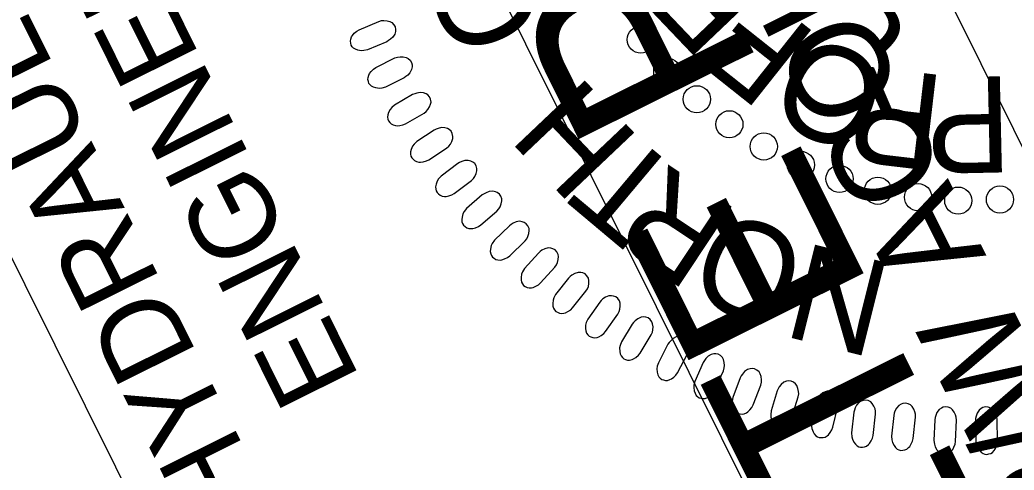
# Model space of a CAD drawing. Extents: x 475112 to 476842, y 500772 to 502767.
# Drawn here: x 475196.2 to 475254.8, y 502233.4 to 502259.9 of the extents above; entities that cross this region are included whole.
import ezdxf

# ---------------------------------------------------------------- set-up
doc = ezdxf.new("R2010")
doc.units = 0
for name, color, linetype in [('Sheet PE Seal Cell', 7, 'Continuous'), ('Sheet Plan CELL', 7, 'Continuous'), ('Sheet Sticker Incomplete CELL', 7, 'Continuous')]:
    doc.layers.add(name, color=color, linetype=linetype)

msp = doc.modelspace()

# ---------------------------------------------------------------- linework, layer by layer
at = {"layer": 'Sheet PE Seal Cell'}
for points in [[(475217.805, 502258.639), (475216.674, 502258.163), (475216.457, 502258.112), (475216.309, 502258.107), (475216.109, 502258.144), (475215.97, 502258.191), (475215.853, 502258.264), (475215.776, 502258.345), (475215.714, 502258.441), (475215.689, 502258.552), (475215.67, 502258.673), (475215.684, 502258.793), (475215.735, 502258.928), (475215.786, 502259.014), (475215.898, 502259.135), (475216.04, 502259.259), (475216.178, 502259.342), (475217.334, 502259.836), (475217.499, 502259.881), (475217.645, 502259.894), (475217.826, 502259.873), (475217.998, 502259.824), (475218.11, 502259.765), (475218.226, 502259.644), (475218.303, 502259.514), (475218.324, 502259.36), (475218.318, 502259.244), (475218.276, 502259.089), (475218.166, 502258.913), (475218.027, 502258.781), (475217.918, 502258.703)], [(475218.832, 502256.515), (475217.733, 502255.969), (475217.52, 502255.905), (475217.371, 502255.89), (475217.17, 502255.915), (475217.028, 502255.953), (475216.907, 502256.018), (475216.825, 502256.094), (475216.757, 502256.186), (475216.725, 502256.295), (475216.698, 502256.415), (475216.705, 502256.535), (475216.748, 502256.673), (475216.793, 502256.763), (475216.897, 502256.889), (475217.031, 502257.023), (475217.164, 502257.114), (475218.286, 502257.68), (475218.448, 502257.736), (475218.593, 502257.757), (475218.776, 502257.748), (475218.951, 502257.71), (475219.065, 502257.658), (475219.189, 502257.544), (475219.273, 502257.419), (475219.304, 502257.268), (475219.306, 502257.152), (475219.274, 502256.993), (475219.174, 502256.811), (475219.044, 502256.671), (475218.941, 502256.586)], [(475219.336, 502255.52), (475218.274, 502254.907), (475218.103, 502254.764), (475218.009, 502254.65), (475217.917, 502254.467), (475217.871, 502254.328), (475217.858, 502254.191), (475217.876, 502254.081), (475217.915, 502253.974), (475217.988, 502253.887), (475218.074, 502253.798), (475218.178, 502253.737), (475218.317, 502253.697), (475218.416, 502253.685), (475218.579, 502253.701), (475218.764, 502253.739), (475218.913, 502253.8), (475220.005, 502254.422), (475220.141, 502254.526), (475220.239, 502254.635), (475220.333, 502254.792), (475220.397, 502254.96), (475220.418, 502255.083), (475220.391, 502255.25), (475220.334, 502255.389), (475220.224, 502255.499), (475220.128, 502255.564), (475219.979, 502255.624), (475219.772, 502255.643), (475219.583, 502255.611), (475219.456, 502255.572)], [(475220.603, 502253.427), (475219.582, 502252.748), (475219.42, 502252.596), (475219.333, 502252.475), (475219.253, 502252.287), (475219.216, 502252.146), (475219.212, 502252.009), (475219.236, 502251.899), (475219.282, 502251.794), (475219.361, 502251.712), (475219.452, 502251.629), (475219.559, 502251.575), (475219.7, 502251.543), (475219.8, 502251.538), (475219.962, 502251.564), (475220.144, 502251.614), (475220.29, 502251.684), (475221.34, 502252.373), (475221.469, 502252.486), (475221.56, 502252.601), (475221.644, 502252.763), (475221.698, 502252.934), (475221.71, 502253.059), (475221.674, 502253.223), (475221.607, 502253.359), (475221.491, 502253.461), (475221.392, 502253.521), (475221.238, 502253.571), (475221.031, 502253.577), (475220.844, 502253.533), (475220.72, 502253.486)], [(475221.993, 502251.459), (475221.017, 502250.718), (475220.865, 502250.555), (475220.784, 502250.429), (475220.718, 502250.237), (475220.689, 502250.093), (475220.693, 502249.956), (475220.725, 502249.848), (475220.777, 502249.746), (475220.86, 502249.669), (475220.957, 502249.593), (475221.067, 502249.545), (475221.211, 502249.522), (475221.31, 502249.523), (475221.47, 502249.56), (475221.649, 502249.621), (475221.79, 502249.699), (475222.795, 502250.454), (475222.916, 502250.574), (475223.001, 502250.694), (475223.073, 502250.862), (475223.116, 502251.036), (475223.121, 502251.162), (475223.074, 502251.323), (475222.999, 502251.454), (475222.877, 502251.549), (475222.774, 502251.602), (475222.618, 502251.643), (475222.411, 502251.636), (475222.227, 502251.58), (475222.106, 502251.526)], [(475223.443, 502249.605), (475222.514, 502248.804), (475222.373, 502248.632), (475222.301, 502248.501), (475222.246, 502248.305), (475222.227, 502248.16), (475222.24, 502248.023), (475222.277, 502247.917), (475222.336, 502247.82), (475222.424, 502247.747), (475222.525, 502247.677), (475222.639, 502247.637), (475222.783, 502247.623), (475222.882, 502247.629), (475223.04, 502247.677), (475223.214, 502247.749), (475223.35, 502247.836), (475224.305, 502248.652), (475224.419, 502248.779), (475224.495, 502248.905), (475224.558, 502249.077), (475224.59, 502249.253), (475224.586, 502249.379), (475224.53, 502249.537), (475224.447, 502249.663), (475224.319, 502249.75), (475224.213, 502249.797), (475224.054, 502249.827), (475223.848, 502249.807), (475223.668, 502249.741), (475223.551, 502249.679)], [(475225.037, 502247.792), (475224.161, 502246.933), (475224.031, 502246.754), (475223.968, 502246.618), (475223.925, 502246.42), (475223.914, 502246.273), (475223.936, 502246.138), (475223.981, 502246.034), (475224.045, 502245.941), (475224.138, 502245.874), (475224.243, 502245.81), (475224.358, 502245.777), (475224.503, 502245.772), (475224.602, 502245.786), (475224.756, 502245.842), (475224.926, 502245.925), (475225.056, 502246.021), (475225.959, 502246.895), (475226.064, 502247.03), (475226.132, 502247.159), (475226.183, 502247.335), (475226.205, 502247.513), (475226.194, 502247.638), (475226.126, 502247.792), (475226.036, 502247.913), (475225.903, 502247.992), (475225.794, 502248.032), (475225.634, 502248.052), (475225.429, 502248.019), (475225.254, 502247.942), (475225.14, 502247.872)], [(475226.748, 502246.185), (475225.928, 502245.273), (475225.809, 502245.085), (475225.754, 502244.946), (475225.724, 502244.745), (475225.723, 502244.599), (475225.753, 502244.465), (475225.804, 502244.365), (475225.875, 502244.275), (475225.971, 502244.215), (475226.08, 502244.157), (475226.198, 502244.131), (475226.342, 502244.135), (475226.44, 502244.155), (475226.59, 502244.221), (475226.755, 502244.315), (475226.878, 502244.418), (475227.724, 502245.347), (475227.821, 502245.488), (475227.88, 502245.622), (475227.921, 502245.801), (475227.931, 502245.979), (475227.912, 502246.104), (475227.835, 502246.254), (475227.737, 502246.368), (475227.599, 502246.438), (475227.489, 502246.471), (475227.327, 502246.482), (475227.125, 502246.437), (475226.955, 502246.348), (475226.846, 502246.271)], [(475228.526, 502244.704), (475227.765, 502243.743), (475227.658, 502243.548), (475227.612, 502243.406), (475227.594, 502243.203), (475227.603, 502243.057), (475227.641, 502242.925), (475227.698, 502242.828), (475227.774, 502242.743), (475227.874, 502242.689), (475227.986, 502242.638), (475228.105, 502242.62), (475228.25, 502242.633), (475228.346, 502242.659), (475228.492, 502242.734), (475228.65, 502242.838), (475228.767, 502242.949), (475229.552, 502243.93), (475229.641, 502244.077), (475229.692, 502244.214), (475229.72, 502244.395), (475229.719, 502244.574), (475229.693, 502244.696), (475229.607, 502244.841), (475229.502, 502244.95), (475229.36, 502245.011), (475229.247, 502245.037), (475229.086, 502245.038), (475228.887, 502244.979), (475228.722, 502244.88), (475228.618, 502244.797)], [(475230.362, 502243.291), (475229.662, 502242.283), (475229.567, 502242.081), (475229.531, 502241.937), (475229.526, 502241.734), (475229.543, 502241.588), (475229.59, 502241.459), (475229.653, 502241.367), (475229.734, 502241.286), (475229.837, 502241.239), (475229.953, 502241.195), (475230.073, 502241.184), (475230.216, 502241.207), (475230.31, 502241.238), (475230.451, 502241.322), (475230.603, 502241.436), (475230.712, 502241.554), (475231.435, 502242.582), (475231.513, 502242.734), (475231.555, 502242.874), (475231.573, 502243.056), (475231.561, 502243.235), (475231.526, 502243.356), (475231.432, 502243.495), (475231.32, 502243.596), (475231.175, 502243.649), (475231.06, 502243.668), (475230.899, 502243.658), (475230.704, 502243.587), (475230.546, 502243.478), (475230.448, 502243.389)], [(475232.283, 502241.993), (475231.648, 502240.943), (475231.566, 502240.736), (475231.538, 502240.59), (475231.546, 502240.387), (475231.573, 502240.243), (475231.627, 502240.117), (475231.696, 502240.028), (475231.782, 502239.953), (475231.888, 502239.911), (475232.006, 502239.876), (475232.126, 502239.872), (475232.267, 502239.903), (475232.36, 502239.941), (475232.495, 502240.034), (475232.639, 502240.157), (475232.741, 502240.282), (475233.398, 502241.353), (475233.467, 502241.51), (475233.501, 502241.653), (475233.506, 502241.835), (475233.483, 502242.013), (475233.441, 502242.131), (475233.337, 502242.264), (475233.22, 502242.358), (475233.071, 502242.402), (475232.956, 502242.413), (475232.796, 502242.394), (475232.606, 502242.31), (475232.455, 502242.191), (475232.363, 502242.096)], [(475234.386, 502240.805), (475233.818, 502239.717), (475233.75, 502239.506), (475233.731, 502239.358), (475233.752, 502239.155), (475233.788, 502239.013), (475233.85, 502238.891), (475233.925, 502238.806), (475234.015, 502238.737), (475234.123, 502238.703), (475234.243, 502238.674), (475234.363, 502238.679), (475234.503, 502238.719), (475234.593, 502238.762), (475234.722, 502238.863), (475234.858, 502238.994), (475234.951, 502239.126), (475235.54, 502240.236), (475235.598, 502240.397), (475235.624, 502240.541), (475235.618, 502240.724), (475235.583, 502240.9), (475235.534, 502241.016), (475235.422, 502241.141), (475235.299, 502241.228), (475235.148, 502241.262), (475235.033, 502241.266), (475234.873, 502241.237), (475234.689, 502241.142), (475234.546, 502241.014), (475234.459, 502240.912)], [(475236.467, 502239.739), (475235.969, 502238.618), (475235.914, 502238.403), (475235.905, 502238.254), (475235.938, 502238.054), (475235.982, 502237.914), (475236.052, 502237.795), (475236.132, 502237.717), (475236.227, 502237.653), (475236.337, 502237.625), (475236.459, 502237.605), (475236.578, 502237.616), (475236.715, 502237.665), (475236.802, 502237.713), (475236.924, 502237.823), (475237.052, 502237.962), (475237.137, 502238.1), (475237.655, 502239.244), (475237.703, 502239.408), (475237.718, 502239.554), (475237.702, 502239.736), (475237.656, 502239.909), (475237.599, 502240.022), (475237.48, 502240.14), (475237.351, 502240.219), (475237.199, 502240.243), (475237.083, 502240.241), (475236.927, 502240.201), (475236.749, 502240.095), (475236.614, 502239.958), (475236.534, 502239.852)], [(475238.642, 502238.824), (475238.214, 502237.674), (475238.173, 502237.455), (475238.173, 502237.306), (475238.219, 502237.108), (475238.272, 502236.972), (475238.349, 502236.858), (475238.434, 502236.784), (475238.532, 502236.726), (475238.644, 502236.706), (475238.767, 502236.692), (475238.885, 502236.712), (475239.018, 502236.769), (475239.102, 502236.823), (475239.217, 502236.94), (475239.336, 502237.087), (475239.412, 502237.228), (475239.857, 502238.404), (475239.895, 502238.571), (475239.901, 502238.717), (475239.873, 502238.898), (475239.816, 502239.069), (475239.754, 502239.177), (475239.627, 502239.288), (475239.493, 502239.358), (475239.34, 502239.373), (475239.224, 502239.363), (475239.07, 502239.314), (475238.899, 502239.197), (475238.774, 502239.051), (475238.7, 502238.941)], [(475240.822, 502238.052), (475240.469, 502236.878), (475240.441, 502236.657), (475240.451, 502236.508), (475240.509, 502236.313), (475240.57, 502236.18), (475240.655, 502236.071), (475240.743, 502236.003), (475240.845, 502235.952), (475240.958, 502235.938), (475241.081, 502235.933), (475241.198, 502235.959), (475241.328, 502236.025), (475241.408, 502236.084), (475241.516, 502236.208), (475241.625, 502236.362), (475241.693, 502236.508), (475242.062, 502237.71), (475242.09, 502237.878), (475242.087, 502238.025), (475242.047, 502238.204), (475241.98, 502238.369), (475241.91, 502238.474), (475241.777, 502238.577), (475241.64, 502238.639), (475241.485, 502238.644), (475241.371, 502238.626), (475241.22, 502238.568), (475241.056, 502238.44), (475240.94, 502238.287), (475240.875, 502238.172)], [(475243.141, 502237.403), (475242.861, 502236.209), (475242.848, 502235.987), (475242.866, 502235.839), (475242.937, 502235.648), (475243.007, 502235.519), (475243.098, 502235.416), (475243.19, 502235.354), (475243.295, 502235.309), (475243.409, 502235.302), (475243.532, 502235.305), (475243.648, 502235.338), (475243.772, 502235.412), (475243.849, 502235.476), (475243.948, 502235.606), (475244.048, 502235.768), (475244.106, 502235.917), (475244.4, 502237.139), (475244.417, 502237.31), (475244.404, 502237.456), (475244.353, 502237.632), (475244.276, 502237.793), (475244.199, 502237.893), (475244.06, 502237.987), (475243.92, 502238.04), (475243.765, 502238.035), (475243.652, 502238.011), (475243.505, 502237.943), (475243.35, 502237.805), (475243.243, 502237.646), (475243.185, 502237.526)], [(475245.344, 502236.796), (475245.206, 502235.577), (475245.219, 502235.355), (475245.255, 502235.21), (475245.348, 502235.029), (475245.432, 502234.909), (475245.534, 502234.818), (475245.634, 502234.767), (475245.743, 502234.734), (475245.857, 502234.741), (475245.979, 502234.758), (475246.09, 502234.805), (475246.205, 502234.893), (475246.273, 502234.965), (475246.357, 502235.106), (475246.437, 502235.278), (475246.477, 502235.434), (475246.625, 502236.682), (475246.622, 502236.853), (475246.592, 502236.997), (475246.521, 502237.165), (475246.426, 502237.316), (475246.337, 502237.407), (475246.188, 502237.484), (475246.043, 502237.52), (475245.889, 502237.497), (475245.78, 502237.46), (475245.642, 502237.375), (475245.505, 502237.22), (475245.417, 502237.049), (475245.373, 502236.923)], [(475247.696, 502236.609), (475247.568, 502235.39), (475247.582, 502235.168), (475247.619, 502235.023), (475247.713, 502234.842), (475247.799, 502234.723), (475247.902, 502234.632), (475248.002, 502234.582), (475248.112, 502234.55), (475248.225, 502234.559), (475248.347, 502234.576), (475248.458, 502234.624), (475248.572, 502234.713), (475248.64, 502234.786), (475248.723, 502234.928), (475248.801, 502235.1), (475248.839, 502235.256), (475248.977, 502236.505), (475248.973, 502236.676), (475248.943, 502236.82), (475248.87, 502236.988), (475248.773, 502237.138), (475248.685, 502237.228), (475248.535, 502237.304), (475248.388, 502237.339), (475248.236, 502237.315), (475248.126, 502237.276), (475247.989, 502237.19), (475247.853, 502237.034), (475247.767, 502236.863), (475247.724, 502236.737)], [(475250.111, 502236.355), (475250.06, 502235.129), (475250.088, 502234.908), (475250.135, 502234.766), (475250.24, 502234.592), (475250.333, 502234.479), (475250.441, 502234.394), (475250.544, 502234.35), (475250.655, 502234.326), (475250.768, 502234.341), (475250.889, 502234.366), (475250.996, 502234.421), (475251.104, 502234.517), (475251.167, 502234.594), (475251.241, 502234.74), (475251.308, 502234.917), (475251.337, 502235.076), (475251.397, 502236.331), (475251.382, 502236.501), (475251.342, 502236.643), (475251.259, 502236.806), (475251.153, 502236.95), (475251.059, 502237.034), (475250.905, 502237.1), (475250.756, 502237.126), (475250.606, 502237.092), (475250.499, 502237.048), (475250.367, 502236.953), (475250.241, 502236.789), (475250.167, 502236.612), (475250.131, 502236.484)], [(475252.506, 502236.308), (475252.533, 502235.081), (475252.574, 502234.863), (475252.63, 502234.724), (475252.745, 502234.557), (475252.845, 502234.449), (475252.959, 502234.372), (475253.064, 502234.334), (475253.177, 502234.317), (475253.289, 502234.339), (475253.408, 502234.372), (475253.51, 502234.433), (475253.613, 502234.535), (475253.671, 502234.617), (475253.735, 502234.768), (475253.791, 502234.949), (475253.811, 502235.108), (475253.791, 502236.366), (475253.765, 502236.534), (475253.717, 502236.672), (475253.624, 502236.83), (475253.509, 502236.967), (475253.41, 502237.045), (475253.252, 502237.102), (475253.102, 502237.118), (475252.954, 502237.075), (475252.85, 502237.023), (475252.725, 502236.921), (475252.609, 502236.749), (475252.546, 502236.568), (475252.519, 502236.437)]]:
    msp.add_lwpolyline(points, close=True, dxfattribs=at)
for centre in [(475232.784, 502258.762), (475234.346, 502256.871), (475236.087, 502255.247), (475238.006, 502253.772), (475240.033, 502252.467), (475242.221, 502251.376), (475244.499, 502250.552), (475246.759, 502249.852), (475249.127, 502249.473), (475251.496, 502249.272), (475253.955, 502249.338)]:
    msp.add_circle(centre, 0.801, dxfattribs=at)
at = {"layer": 'Sheet Plan CELL'}
msp.add_lwpolyline([(475217.863, 502201.351), (475173.331, 502290.874), (475274.068, 502340.984), (475318.607, 502251.45)], close=True, dxfattribs=at)
at = {"layer": 'Sheet Sticker Incomplete CELL'}
msp.add_lwpolyline([(475300.957, 502160.586), (475279.915, 502150.122), (475214.46, 502281.746), (475235.502, 502292.21)], close=True, dxfattribs=at)

# ---------------------------------------------------------------- texts
at = {"layer": 'Sheet PE Seal Cell'}
for s, rotation, p in [('E', 133.60936, (475240.42, 502261.294)), ('C', 114.02842, (475227.351, 502259.607)), ('F', 141.54916, (475243.307, 502258.943)), ('O', 157.42876, (475247.764, 502257.03)), ('R', 173.30835, (475250.807, 502256.63)), ('H', 133.49649, (475232.825, 502252.83)), ('P', 181.24815, (475254.568, 502256.616)), ('T', 139.98584, (475235.503, 502250.612)), ('R', 146.4752, (475238.655, 502248.582)), ('O', 159.45391, (475242.914, 502246.819)), ('N', 165.94327, (475247.767, 502245.494))]:
    msp.add_text(s, height=5.669, rotation=rotation, dxfattribs=at).set_placement(p)
at = {"layer": 'Sheet Plan CELL'}
for s, p in [('HYDRAULICS', (475210.813, 502231.867)), ('ENGINEER', (475216.268, 502238.781))]:
    msp.add_text(s, height=5.0001, rotation=116.44074, dxfattribs=at).set_placement(p)
at = {"layer": 'Sheet Sticker Incomplete CELL'}
for s, height, p in [('INCOMPLETE PLANS', 11.52, (475286.496, 502163.39)), ('DO NOT USE FOR R/W ACQUISITION', 5.76, (475291.271, 502169.395))]:
    msp.add_text(s, height=height, rotation=116.44074, dxfattribs=at).set_placement(p)

doc.saveas('drawing.dxf')
